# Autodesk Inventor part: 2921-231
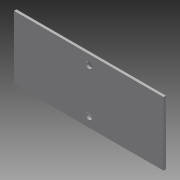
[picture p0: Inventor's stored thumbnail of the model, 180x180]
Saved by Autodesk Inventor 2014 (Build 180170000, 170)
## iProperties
Company: NHTSA/VRTC
Created: 2012-08
Part Number: 2921-231
Material: Steel, Mild
Document SubType Name: Modeling
Designer: Mike Vanvoorhis
Density: 7.86 g/cm^3
Mass: 3172.12 g
Surface Area: 1347.61 cm^2
Volume: 403.578 cm^3
Project: CHILD SIDE IMPACT SLED
Description: HONEYCOMB FRAME BASE PLATE
Stock Number: PL 6.4 (1/4") X 165.1 (6 1/2") X 387.4 (15 1/4")
Appearance: Steel
Author: Dave Walker
Title: Honeycomb Frame Base Plate
Subject: Child Side Impact Sled
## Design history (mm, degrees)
sketch "Sketch1"
  geometry: L1 (0, 0)-(387.35, 0); L2 (387.35, 0)-(387.35, 165.1); L3 (387.35, 165.1)-(0, 165.1); L4 (0, 165.1)-(0, 0)
  constraints: 8 end point, 2 parallel, 1 horizontal, 1 perpendicular
  dimensions: "d0" = 387.35 distance of L3.end L2.end; "d1" = 165.1 distance of L2.end L1.end
extrude "Extrusion1" new body sketch "Sketch1" distance "d2" = 6.35; taper "d3" = 0 deg
sketch "Sketch2"
  geometry: L1 (0, 0)-(387.35, 0) reference; L2 (387.35, 165.1)-(0, 165.1) reference; L3 (0, 165.1)-(0, 0) reference; L4 (193.675, 165.1)-(193.675, 139.7); L5 (193.675, 0)-(193.675, 25.4)
  constraints: 4 end point, 2 midpoint, 1 collinear, 1 parallel
  dimensions: "d4" = 25.4 distance of L4.start L4.end; "d5" = 25.4 distance of L5.start L5.end
hole "Hole1" sketch "Sketch2" at (193.675, 139.7), (193.675, 25.4) diameter "d6" = 15.875; stored, may be unused: countersink angle "d10" = 82 deg, drill point angle "d12" = 118 deg; dims "d7" = 19.05, "d8" = 9.525, "d9" = 6.35, "d11" = 25.4
body "Solid1"
